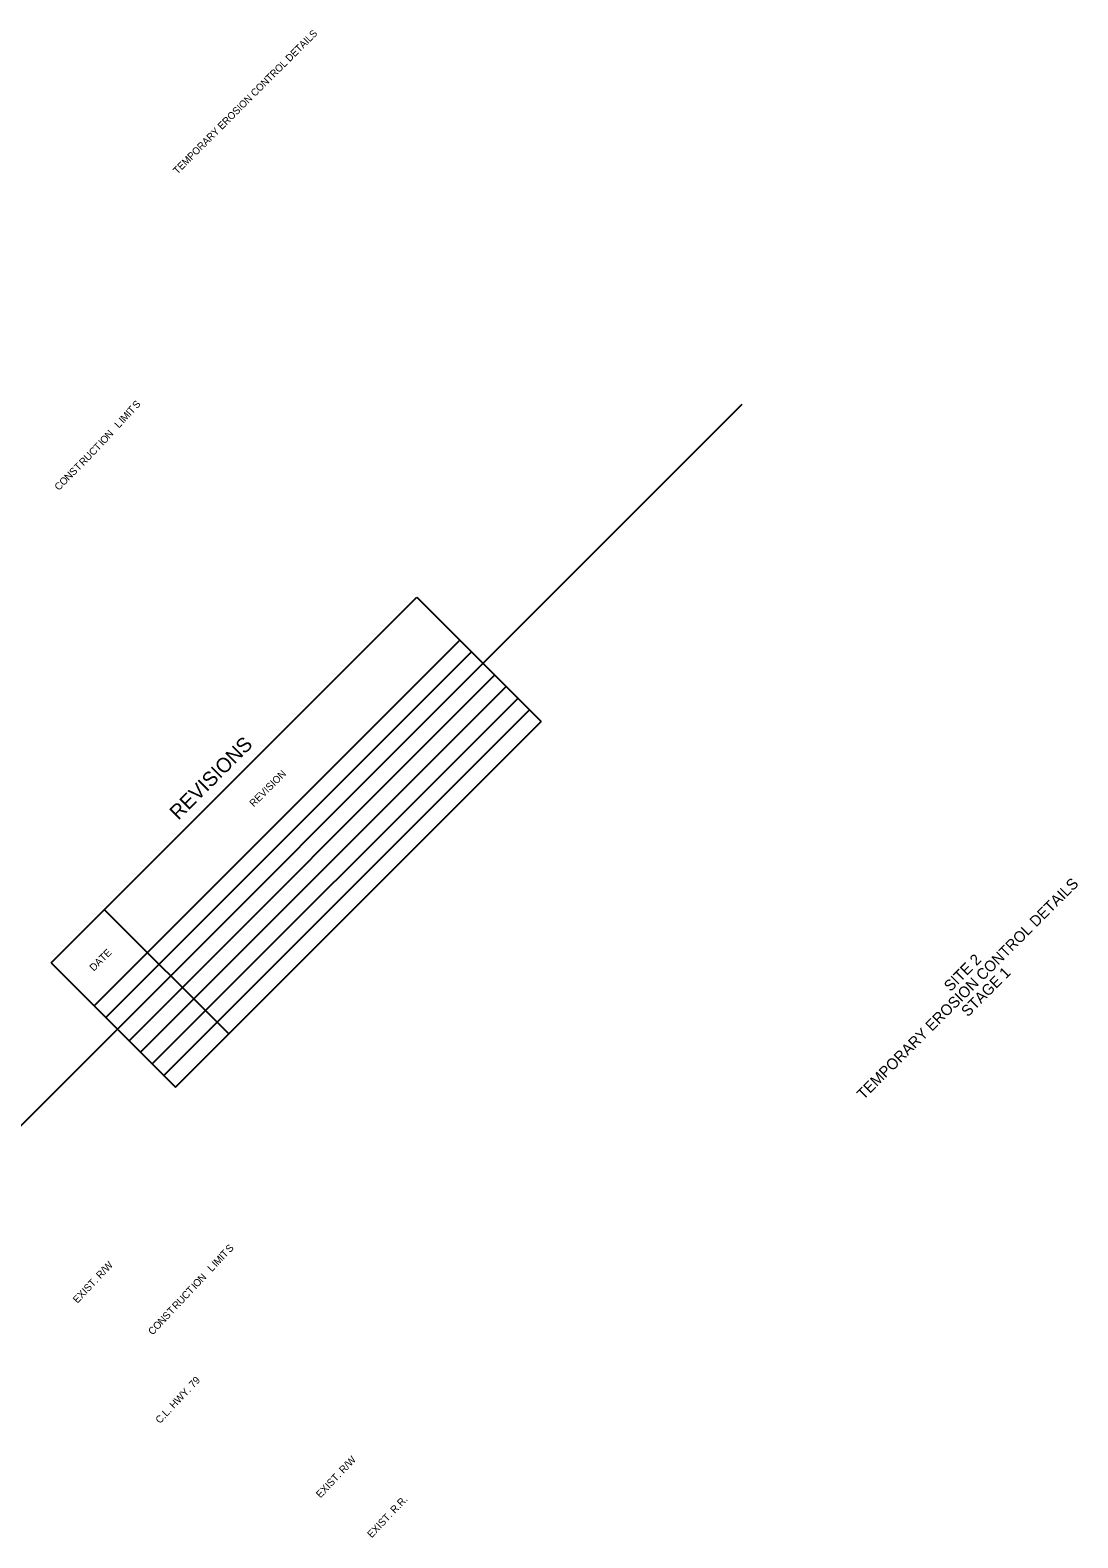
# Model space of a CAD drawing. Extents: x 1388120 to 1389841, y 1944307 to 1945760.
# Drawn here: x 1388980 to 1389841, y 1944521 to 1945760 of the extents above; entities that cross this region are included whole.
import ezdxf

# ---------------------------------------------------------------- set-up
doc = ezdxf.new("R2010")
doc.units = 0
for name, color, linetype in [('1', 7, 'Continuous'), ('60', 7, 'Continuous'), ('Default', 7, 'Continuous'), ('R_Draft', 7, 'Continuous')]:
    doc.layers.add(name, color=color, linetype=linetype)

msp = doc.modelspace()

# ---------------------------------------------------------------- linework, layer by layer
at = {"layer": '1'}
for p, q in [((1389352.4, 1945239.6), (1389565.3, 1945452.4)), ((1388849.6, 1944736.7), (1389051.9, 1944939.1))]:
    msp.add_line(p, q, dxfattribs=at)
at = {"layer": 'Default'}
for p, q in [((1388997.5, 1944993.5), (1389298, 1945294)), ((1389298, 1945294), (1389400.2, 1945191.9)), ((1389032.8, 1944958.2), (1389333.4, 1945258.7)), ((1389042.4, 1944948.6), (1389342.9, 1945249.1)), ((1389051.9, 1944939.1), (1389352.4, 1945239.6)), ((1389061.5, 1944929.5), (1389362, 1945230.1)), ((1389061.5, 1944929.5), (1389362, 1945230.1)), ((1389071, 1944920), (1389371.5, 1945220.5)), ((1389080.6, 1944910.4), (1389381.1, 1945211)), ((1389090.1, 1944900.9), (1389390.6, 1945201.4)), ((1389099.7, 1944891.4), (1389400.2, 1945191.9)), ((1389041.2, 1945037.2), (1389143.4, 1944935.1)), ((1388997.5, 1944993.5), (1389099.7, 1944891.4))]:
    msp.add_line(p, q, dxfattribs=at)

# ---------------------------------------------------------------- texts
at = {"layer": '1'}
msp.add_text('TEMPORARY EROSION CONTROL DETAILS', height=5.862, rotation=45, dxfattribs=at).set_placement((1389101.2, 1945641.1))
at = {"layer": '60'}
for s, p in [('TEMPORARY EROSION CONTROL DETAILS', (1389665, 1944880.4)), ('SITE 2', (1389736.5, 1944969.3)), ('STAGE 1', (1389750.7, 1944948.6))]:
    msp.add_text(s, height=9, rotation=45, dxfattribs=at).set_placement(p)
at = {"layer": 'Default'}
for s, height, p in [('REVISIONS', 12, (1389102.1, 1945110.2)), ('REVISION', 6, (1389164, 1945121.2)), ('DATE', 6, (1389032.6, 1944986.2))]:
    msp.add_text(s, height=height, rotation=45, dxfattribs=at).set_placement(p)
at = {"layer": 'R_Draft'}
for s, rotation, p in [('T', 47.0121, (1389063.9, 1945444)), ('S', 47.0121, (1389067.9, 1945448.3)), ('I', 47.1751, (1389056.9, 1945436.3)), ('M', 47.4213, (1389058.2, 1945437.8)), ('I', 47.4213, (1389062.6, 1945442.5)), ('O', 47.5738, (1389041.4, 1945419.4)), ('N', 47.7045, (1389045.3, 1945423.7)), ('L', 47.1751, (1389053.2, 1945432.4)), ('C', 45.7542, (1389032.1, 1945409.7)), ('T', 45.7542, (1389036, 1945413.7)), ('I', 47.5738, (1389040.1, 1945418)), ('T', 44.7635, (1389019.9, 1945397.3)), ('R', 45.9839, (1389024.1, 1945401.4)), ('U', 45.9839, (1389028, 1945405.5)), ('O', 45.15, (1389007.8, 1945385.1)), ('N', 45.1807, (1389011.9, 1945389.3)), ('S', 44.7635, (1389015.9, 1945393.3)), ('C', 45.15, (1389003.8, 1945381.1)), ('T', 46.8042, (1389140.4, 1944750.7)), ('S', 46.8042, (1389144.4, 1944754.9)), ('EXIST. R/W', 46.6607, (1389019.1, 1944713.3)), ('I', 46.8038, (1389133.3, 1944743.1)), ('M', 46.8038, (1389134.7, 1944744.5)), ('I', 46.8038, (1389139.1, 1944749.2)), ('O', 46.8095, (1389117.6, 1944726.4)), ('N', 46.806, (1389121.6, 1944730.6)), ('L', 46.8073, (1389129.6, 1944739.2)), ('U', 46.9645, (1389104.5, 1944712.3)), ('C', 46.8628, (1389108.4, 1944716.5)), ('T', 46.8095, (1389112.3, 1944720.7)), ('I', 46.8095, (1389116.3, 1944724.9)), ('T', 46.9373, (1389096.6, 1944703.9)), ('R', 46.9645, (1389100.6, 1944708.2)), ('O', 46.6117, (1389084.8, 1944691.4)), ('N', 46.6117, (1389088.8, 1944695.6)), ('S', 46.9373, (1389092.7, 1944699.7)), ('C', 46.587, (1389080.9, 1944687.2)), ('C.L. HWY. 79', 46.736, (1389086.9, 1944614.4)), ('EXIST. R/W', 46.6607, (1389218.8, 1944553.3)), ('EXIST. R.R.', 46.6607, (1389260.9, 1944520.5))]:
    msp.add_text(s, height=6, rotation=rotation, dxfattribs=at).set_placement(p)

doc.saveas('drawing.dxf')
